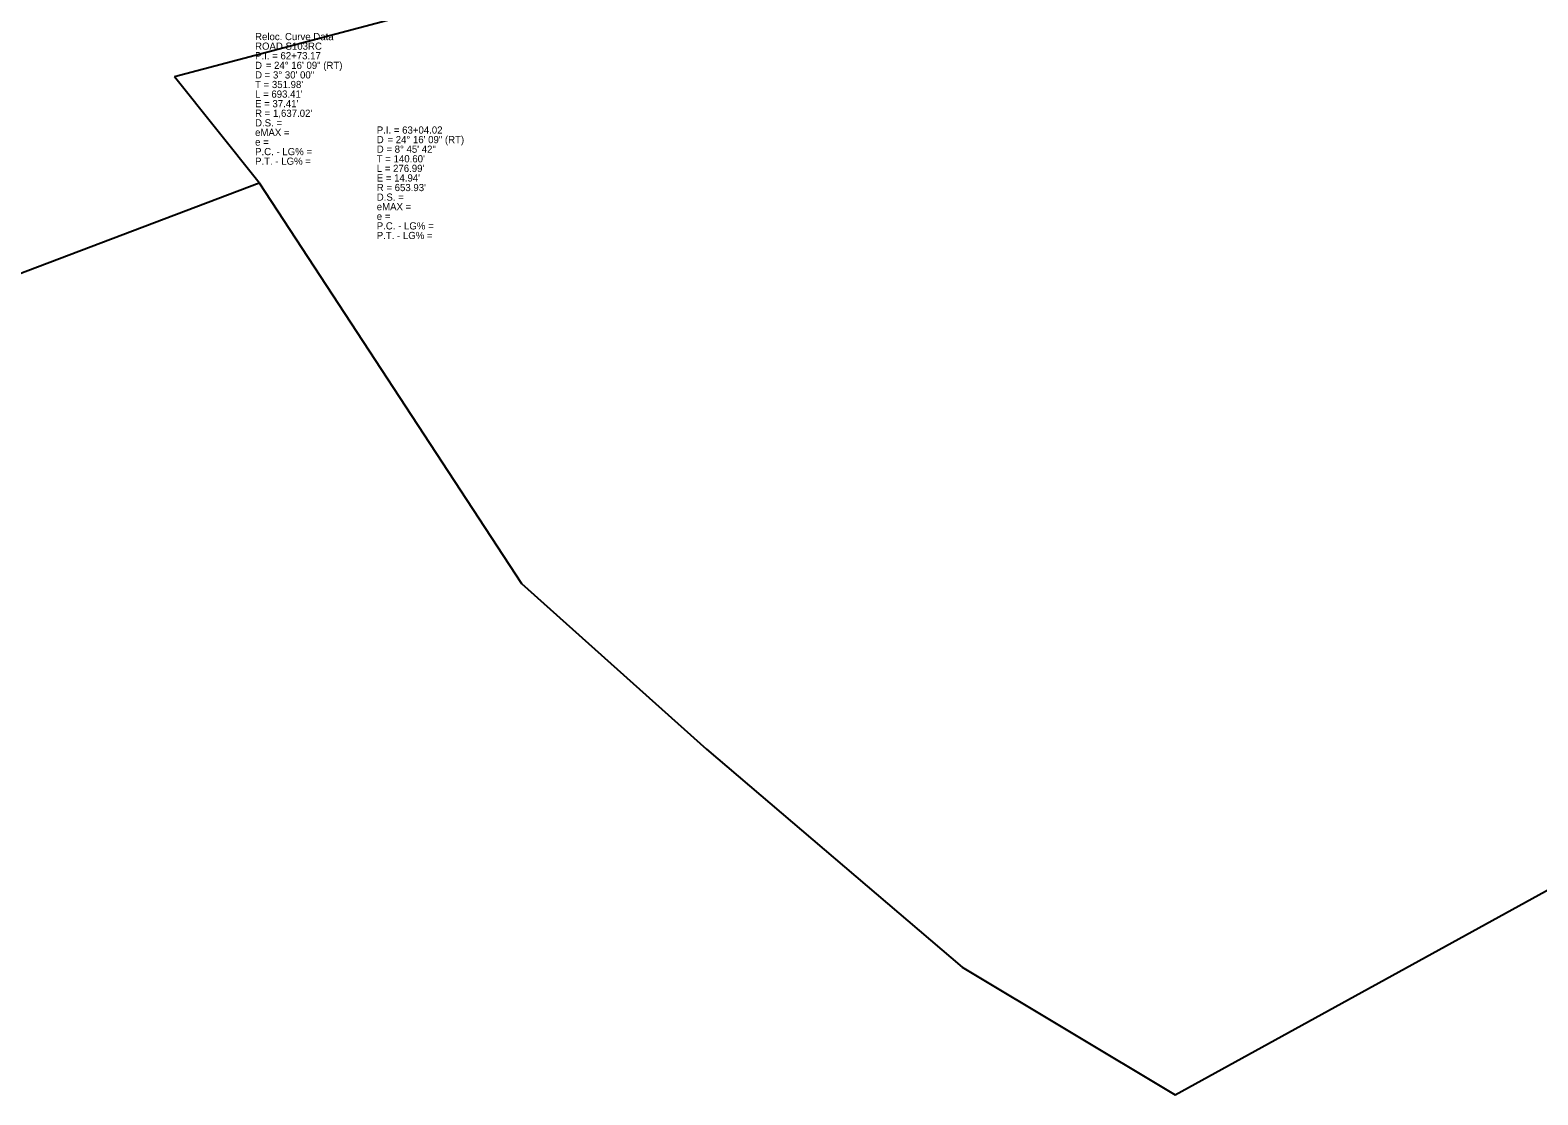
# Model space of a CAD drawing. Extents: x 1964982 to 1970527, y 1116335 to 1119906.
# Drawn here: x 1967748 to 1969320, y 1116335 to 1117446 of the extents above; entities that cross this region are included whole.
import ezdxf

# ---------------------------------------------------------------- set-up
doc = ezdxf.new("R2010")
doc.units = 0
doc.layers.add('RD_EX_DV_Prop', color=7, linetype='Continuous')
doc.layers.add('RD_HC_txCode', color=7, linetype='Continuous')

msp = doc.modelspace()

# ---------------------------------------------------------------- linework, layer by layer
at = {"layer": 'RD_EX_DV_Prop'}
for p, q in [((1968204.3, 1117478.1), (1967898.1, 1117396.7)), ((1967986.4, 1117286.2), (1967898.1, 1117396.7)), ((1967582.6, 1117133.3), (1967986.4, 1117286.2)), ((1967986.4, 1117286.2), (1968260.1, 1116868.2)), ((1968260.1, 1116868.2), (1968452.8, 1116695.3)), ((1968941.8, 1116334.8), (1969776.6, 1116794.1)), ((1968452.8, 1116695.3), (1968719.5, 1116468.1)), ((1968719.5, 1116468.1), (1968941.8, 1116334.8))]:
    msp.add_line(p, q, dxfattribs=at)

# ---------------------------------------------------------------- texts
at = {"layer": 'RD_HC_txCode'}
for s, p in [('Reloc. Curve Data', (1967982.1, 1117435.1)), ('ROAD S103RC', (1967982.1, 1117425.1)), ('P.I. = 62+73.17', (1967982.1, 1117415.1)), ('D', (1967982.1, 1117405.1)), ('D = 3%%d 30\' 00"', (1967982.1, 1117395.1)), ('    = 24%%d 16\' 09" (RT)', (1967982.1, 1117405.1)), ("T = 351.98'", (1967982.1, 1117385.1)), ("L = 693.41'", (1967982.1, 1117375.1)), ("E = 37.41'", (1967982.1, 1117365.1)), ("R = 1,637.02'", (1967982.1, 1117355.1)), ('eMAX = ', (1967982.1, 1117335.1)), ('D.S. =', (1967982.1, 1117345.1)), ('P.I. = 63+04.02', (1968109, 1117337.6)), ('e = ', (1967982.1, 1117325.1)), ('P.C. - LG% = ', (1967982.1, 1117315.1)), ('D', (1968109, 1117327.6)), ('D = 8%%d 45\' 42"', (1968109, 1117317.6)), ('    = 24%%d 16\' 09" (RT)', (1968109, 1117327.6)), ('P.T. - LG% = ', (1967982.1, 1117305.1)), ("T = 140.60'", (1968109, 1117307.6)), ("L = 276.99'", (1968109, 1117297.6)), ("E = 14.94'", (1968109, 1117287.6)), ("R = 653.93'", (1968109, 1117277.6)), ('D.S. = ', (1968109, 1117267.6)), ('eMAX = ', (1968109, 1117257.6)), ('e = ', (1968109, 1117247.6)), ('P.C. - LG% = ', (1968109, 1117237.6)), ('P.T. - LG% = ', (1968109, 1117227.6))]:
    msp.add_text(s, height=7.5, dxfattribs=at).set_placement(p)

doc.saveas('drawing.dxf')
